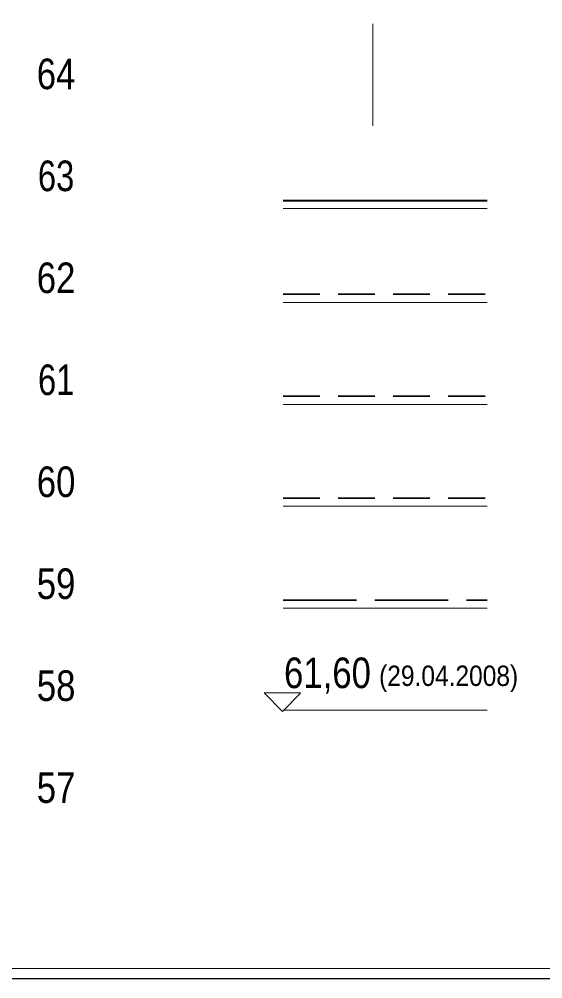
# Model space of a CAD drawing. Extents: x 640121 to 640955, y 6441885 to 6442246.
# Drawn here: x 640466.2 to 640517.6, y 6441889.4 to 6441983.5 of the extents above; entities that cross this region are included whole.
import ezdxf
from ezdxf.enums import TextEntityAlignment as Align

# ---------------------------------------------------------------- set-up
doc = ezdxf.new("R2010")
doc.units = 0
doc.header["$LTSCALE"] = 1.2
doc.linetypes.add('LONG_DASHED', pattern=[7.5, 6, -1.5])
doc.linetypes.add('MEDIUM_DASHED', pattern=[4.5, 3, -1.5])
doc.layers.add('30', color=7, linetype='Continuous', lineweight=13)
doc.layers.add('50', color=7, linetype='Continuous', lineweight=13)

msp = doc.modelspace()

# ---------------------------------------------------------------- linework, layer by layer
at = {"layer": '50'}
for p, q in [((640500.88, 6441973.05), (640500.88, 6441983.05)), ((640492.09, 6441964.94), (640512.09, 6441964.94)), ((640492.09, 6441955.74), (640512.09, 6441955.74)), ((640492.09, 6441945.74), (640512.09, 6441945.74)), ((640492.09, 6441935.74), (640512.09, 6441935.74)), ((640492.09, 6441925.74), (640512.09, 6441925.74)), ((640492.09, 6441915.74), (640512.09, 6441915.74))]:
    msp.add_line(p, q, dxfattribs=at)
at = {"layer": '50', "lineweight": 40}
msp.add_line((640492.09, 6441965.74), (640512.09, 6441965.74), dxfattribs=at)
at = {"layer": '50', "linetype": 'MEDIUM_DASHED', "lineweight": 35}
for p, q in [((640492.09, 6441956.54), (640512.09, 6441956.54)), ((640492.09, 6441946.54), (640512.09, 6441946.54)), ((640492.09, 6441936.54), (640512.09, 6441936.54))]:
    msp.add_line(p, q, dxfattribs=at)
at = {"layer": '50', "linetype": 'LONG_DASHED', "lineweight": 35}
msp.add_line((640492.09, 6441926.54), (640512.09, 6441926.54), dxfattribs=at)
at = {"layer": '50', "lineweight": 25}
for points in [[(640121.33, 6442246.16), (640955.23, 6442246.16), (640955.23, 6441889.4), (640121.33, 6441889.4)], [(640490.22, 6441917.44), (640492.01, 6441915.62), (640493.78, 6441917.43)]]:
    msp.add_lwpolyline(points, close=True, dxfattribs=at)
at = {"layer": '50'}
msp.add_lwpolyline([(640122.33, 6442245.16), (640954.23, 6442245.16), (640954.23, 6441890.4), (640122.33, 6441890.4)], close=True, dxfattribs=at)

# ---------------------------------------------------------------- texts
at = {"layer": '30'}
for s, width, p in [('64', 0.85, (640469.795, 6441976.65)), ('63', 0.8, (640469.795, 6441966.65)), ('62', 0.85, (640469.795, 6441956.65)), ('61', 0.8, (640469.805, 6441946.65)), ('60', 0.85, (640469.795, 6441936.65)), ('59', 0.85, (640469.795, 6441926.65)), ('58', 0.85, (640469.8, 6441916.65)), ('57', 0.85, (640469.795, 6441906.65))]:
    msp.add_text(s, height=3, dxfattribs=dict(at, width=width)).set_placement(p, align=Align.CENTER)
at = {"layer": '50'}
for s, height, width, p in [('61,60', 3, 0.85, (640496.43, 6441917.91)), ('(29.04.2008)', 2, 0.9, (640508.32, 6441918.12))]:
    msp.add_text(s, height=height, dxfattribs=dict(at, width=width)).set_placement(p, align=Align.CENTER)

doc.saveas('drawing.dxf')
